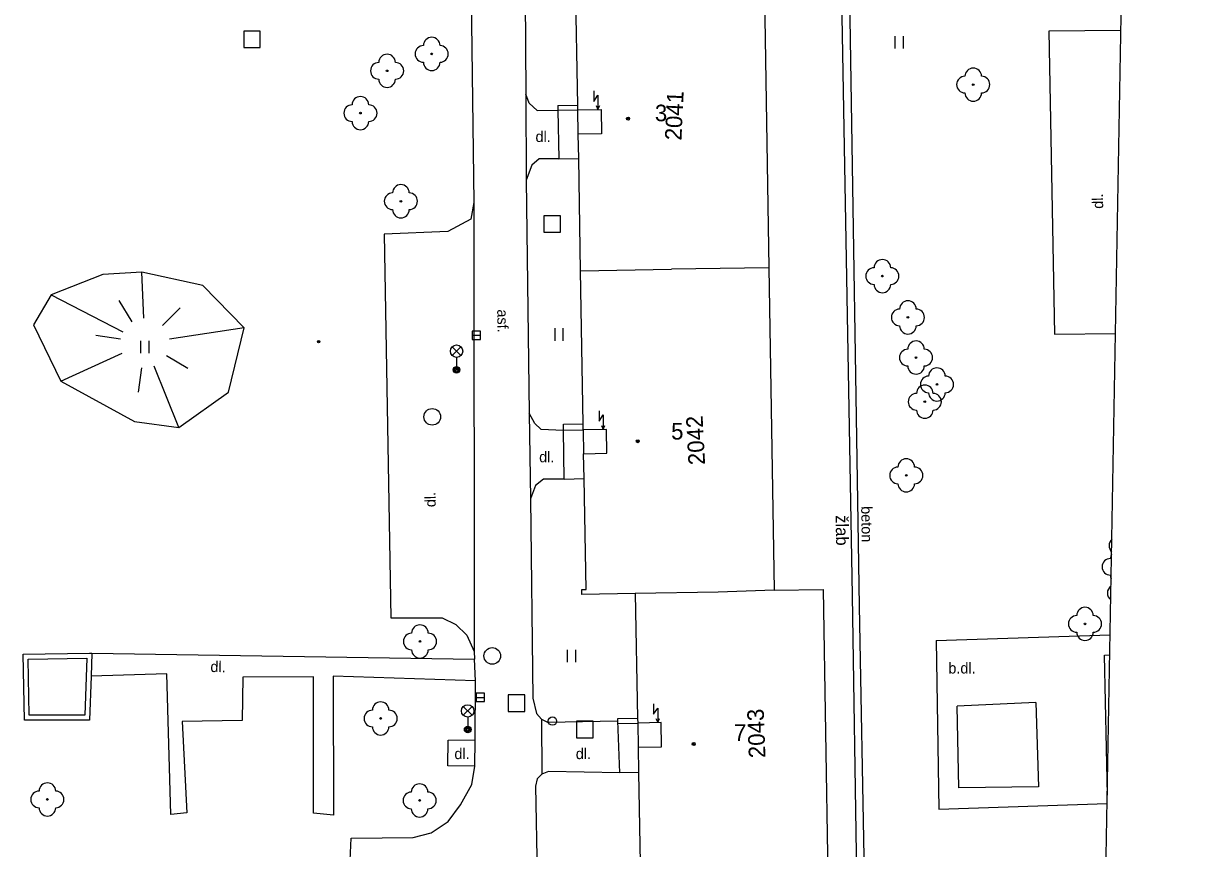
# Model space of a CAD drawing. Extents: x -641829 to -641525, y -1114855 to -1114359.
# Drawn here: x -641595.2 to -641525.3, y -1114618.1 to -1114568.4 of the extents above; entities that cross this region are included whole.
import ezdxf

# ---------------------------------------------------------------- set-up
doc = ezdxf.new("R2010")
doc.units = 0
for name, color, linetype in [('Vrstva 1', 7, 'Continuous'), ('Vrstva 10', 7, 'Continuous'), ('Vrstva 11', 7, 'Continuous'), ('Vrstva 14', 7, 'Continuous'), ('Vrstva 15', 7, 'Continuous'), ('Vrstva 20', 7, 'Continuous'), ('Vrstva 22', 7, 'Continuous'), ('Vrstva 24', 7, 'Continuous'), ('Vrstva 26', 7, 'Continuous'), ('Vrstva 27', 7, 'Continuous'), ('Vrstva 28', 7, 'Continuous'), ('Vrstva 33', 7, 'Continuous'), ('Vrstva 36', 7, 'Continuous'), ('Vrstva 39', 7, 'Continuous'), ('Vrstva 40', 7, 'Continuous'), ('Vrstva 42', 7, 'Continuous'), ('Vrstva 46', 7, 'Continuous'), ('Vrstva 47', 7, 'Continuous'), ('Vrstva 5', 7, 'Continuous')]:
    doc.layers.add(name, color=color, linetype=linetype)

msp = doc.modelspace()

# ---------------------------------------------------------------- linework, layer by layer
at = {"layer": 'Vrstva 1'}
msp.add_line((-641533.66, -1114832.21), (-641525.3, -1114362.64), dxfattribs=at)
at = {"layer": 'Vrstva 10'}
for p, q in [((-641564.94, -1114557.27), (-641564.87, -1114572.64)), ((-641568.18, -1114564.7), (-641568.01, -1114579.17)), ((-641564.87, -1114572.64), (-641564.84, -1114577.82)), ((-641564.84, -1114577.82), (-641564.66, -1114591.88)), ((-641568.01, -1114579.17), (-641567.97, -1114606.24)), ((-641564.66, -1114591.88), (-641564.58, -1114597.03)), ((-641564.58, -1114597.03), (-641564.44, -1114609.04)), ((-641567.97, -1114606.24), (-641567.96, -1114606.7)), ((-641567.9, -1114608), (-641567.96, -1114606.7)), ((-641567.91, -1114611.55), (-641567.9, -1114608)), ((-641564.44, -1114609.04), (-641564.23, -1114609.98)), ((-641564.23, -1114609.98), (-641563.92, -1114610.31)), ((-641563.92, -1114610.31), (-641563.89, -1114613.62)), ((-641567.93, -1114613.15), (-641567.91, -1114611.55)), ((-641568.13, -1114614.24), (-641567.93, -1114613.15)), ((-641564.18, -1114613.91), (-641564.29, -1114614.35)), ((-641563.89, -1114613.62), (-641564.18, -1114613.91)), ((-641568.8, -1114615.48), (-641568.13, -1114614.24)), ((-641564.29, -1114614.35), (-641564.01, -1114628.78)), ((-641569.55, -1114616.47), (-641568.8, -1114615.48)), ((-641570.58, -1114617.17), (-641569.55, -1114616.47)), ((-641571.65, -1114617.45), (-641570.58, -1114617.17)), ((-641575.8, -1114626.45), (-641575.4, -1114617.49)), ((-641575.4, -1114617.49), (-641571.65, -1114617.45))]:
    msp.add_line(p, q, dxfattribs=at)
at = {"layer": 'Vrstva 11'}
for p, q in [((-641544.73, -1114603.5), (-641545.7, -1114543.89)), ((-641546.21, -1114544.41), (-641545.19, -1114602.86)), ((-641528.971, -1114568.817), (-641533.32, -1114568.84)), ((-641533.32, -1114568.84), (-641532.97, -1114587.11)), ((-641564.67, -1114573.19), (-641564.87, -1114572.64)), ((-641564.67, -1114573.19), (-641564.19, -1114573.64)), ((-641562.94, -1114573.32), (-641561.73, -1114573.3)), ((-641562.94, -1114573.32), (-641562.93, -1114573.62)), ((-641564.19, -1114573.64), (-641562.93, -1114573.62)), ((-641562.93, -1114573.62), (-641561.72, -1114573.6)), ((-641562.93, -1114573.62), (-641562.88, -1114576.55)), ((-641564.06, -1114576.54), (-641564.51, -1114576.92)), ((-641562.88, -1114576.55), (-641564.06, -1114576.54)), ((-641562.88, -1114576.55), (-641561.67, -1114576.53)), ((-641564.51, -1114576.92), (-641564.84, -1114577.82)), ((-641568.01, -1114579.17), (-641568.18, -1114580.17)), ((-641568.18, -1114580.17), (-641569.56, -1114580.92)), ((-641569.56, -1114580.92), (-641573.41, -1114581.09)), ((-641573.41, -1114581.09), (-641573.01, -1114604.2)), ((-641532.97, -1114587.11), (-641529.296, -1114587.071)), ((-641564.32, -1114592.5), (-641564.66, -1114591.88)), ((-641564.32, -1114592.5), (-641563.95, -1114592.84)), ((-641563.95, -1114592.84), (-641562.6, -1114592.89)), ((-641562.6, -1114592.53), (-641561.4, -1114592.51)), ((-641562.6, -1114592.89), (-641562.6, -1114592.53)), ((-641562.6, -1114592.89), (-641561.4, -1114592.87)), ((-641562.55, -1114595.84), (-641562.6, -1114592.89)), ((-641564.29, -1114596.23), (-641564.58, -1114597.03)), ((-641563.8, -1114595.85), (-641564.29, -1114596.23)), ((-641562.55, -1114595.84), (-641563.8, -1114595.85)), ((-641562.55, -1114595.84), (-641561.35, -1114595.81)), ((-641545.19, -1114602.86), (-641544.57, -1114641.53)), ((-641544.03, -1114641.87), (-641544.73, -1114603.5)), ((-641573.01, -1114604.2), (-641569.91, -1114604.21)), ((-641569.91, -1114604.21), (-641569.08, -1114604.61)), ((-641569.08, -1114604.61), (-641568.43, -1114605.24)), ((-641568.43, -1114605.24), (-641567.97, -1114606.24)), ((-641540.11, -1114605.58), (-641529.619, -1114605.221)), ((-641540.11, -1114605.58), (-641539.95, -1114615.74)), ((-641595.18, -1114606.39), (-641591.17, -1114606.33)), ((-641595.11, -1114610.38), (-641595.18, -1114606.39)), ((-641594.87, -1114606.69), (-641591.34, -1114606.63)), ((-641594.82, -1114610.08), (-641594.87, -1114606.69)), ((-641591.34, -1114606.63), (-641591.47, -1114610.07)), ((-641591.17, -1114606.33), (-641591.03, -1114606.33)), ((-641591.03, -1114606.33), (-641591.08, -1114607.73)), ((-641591.03, -1114606.33), (-641567.96, -1114606.7)), ((-641529.97, -1114606.45), (-641529.64, -1114606.439)), ((-641529.791, -1114614.887), (-641529.97, -1114606.45)), ((-641586.52, -1114607.59), (-641591.08, -1114607.73)), ((-641586.28, -1114616.05), (-641586.52, -1114607.59)), ((-641591.08, -1114607.73), (-641591.18, -1114610.37)), ((-641581.94, -1114607.78), (-641581.98, -1114610.39)), ((-641577.66, -1114607.76), (-641581.94, -1114607.78)), ((-641577.66, -1114615.98), (-641577.66, -1114607.76)), ((-641576.48, -1114607.73), (-641576.47, -1114616.09)), ((-641567.9, -1114608), (-641576.48, -1114607.73)), ((-641534.11, -1114609.3), (-641538.85, -1114609.53)), ((-641538.74, -1114614.46), (-641538.85, -1114609.53)), ((-641534.11, -1114609.3), (-641533.94, -1114614.38)), ((-641591.18, -1114610.37), (-641595.11, -1114610.38)), ((-641591.47, -1114610.07), (-641594.82, -1114610.08)), ((-641581.98, -1114610.39), (-641585.59, -1114610.46)), ((-641563.92, -1114610.31), (-641563.55, -1114610.49)), ((-641563.55, -1114610.49), (-641559.32, -1114610.42)), ((-641559.32, -1114610.27), (-641558.12, -1114610.25)), ((-641559.32, -1114610.42), (-641559.32, -1114610.27)), ((-641559.2, -1114613.55), (-641559.32, -1114610.42)), ((-641585.59, -1114610.46), (-641585.31, -1114615.96)), ((-641559.31, -1114610.57), (-641558.11, -1114610.55)), ((-641569.57, -1114613.12), (-641569.55, -1114611.58)), ((-641569.55, -1114611.58), (-641567.91, -1114611.55)), ((-641567.93, -1114613.15), (-641569.57, -1114613.12)), ((-641563.49, -1114613.47), (-641563.89, -1114613.62)), ((-641559.2, -1114613.55), (-641563.49, -1114613.47)), ((-641558.06, -1114613.53), (-641559.2, -1114613.55)), ((-641533.94, -1114614.38), (-641538.74, -1114614.46)), ((-641585.31, -1114615.96), (-641586.28, -1114616.05)), ((-641576.47, -1114616.09), (-641577.66, -1114615.98)), ((-641539.95, -1114615.74), (-641529.8, -1114615.401))]:
    msp.add_line(p, q, dxfattribs=at)
at = {"layer": 'Vrstva 14'}
for p, q in [((-641590.37, -1114583.51), (-641593.5, -1114584.73)), ((-641588.03, -1114583.38), (-641590.37, -1114583.51)), ((-641584.34, -1114584.17), (-641588.03, -1114583.38)), ((-641581.85, -1114586.73), (-641584.34, -1114584.17)), ((-641593.5, -1114584.73), (-641594.55, -1114586.54)), ((-641594.55, -1114586.54), (-641592.91, -1114589.94)), ((-641582.8, -1114590.6), (-641581.85, -1114586.73)), ((-641592.91, -1114589.94), (-641588.47, -1114592.37)), ((-641585.79, -1114592.74), (-641582.8, -1114590.6)), ((-641588.47, -1114592.37), (-641585.79, -1114592.74))]:
    msp.add_line(p, q, dxfattribs=at)
at = {"layer": 'Vrstva 15'}
for p, q in [((-641587.9, -1114586.14), (-641588.03, -1114583.38)), ((-641593.5, -1114584.73), (-641589.17, -1114586.96)), ((-641589.41, -1114585.08), (-641588.62, -1114586.36)), ((-641586.77, -1114586.58), (-641585.71, -1114585.53)), ((-641590.8, -1114587.16), (-641589.32, -1114587.4)), ((-641581.85, -1114586.73), (-641586.35, -1114587.42)), ((-641592.91, -1114589.94), (-641589.2, -1114588.26)), ((-641586.54, -1114588.4), (-641585.25, -1114589.16)), ((-641588.04, -1114589.13), (-641588.24, -1114590.61)), ((-641585.79, -1114592.74), (-641587.28, -1114589.03))]:
    msp.add_line(p, q, dxfattribs=at)
at = {"layer": 'Vrstva 20'}
for radius in [0.075, 0.0204]:
    msp.add_circle((-641577.36, -1114587.56), radius, dxfattribs=at)
at = {"layer": 'Vrstva 22'}
for centre in [(-641570.54, -1114570.22), (-641573.23, -1114571.24), (-641537.88, -1114572.07), (-641574.84, -1114573.79), (-641572.4, -1114579.1), (-641543.36, -1114583.61), (-641541.82, -1114586.1), (-641541.33, -1114588.52), (-641540.07, -1114590.14), (-641540.8, -1114591.18), (-641541.92, -1114595.62), (-641531.14, -1114604.57), (-641571.25, -1114605.63), (-641573.62, -1114610.27), (-641593.72, -1114615.15), (-641571.27, -1114615.21)]:
    msp.add_circle(centre, 0.05, dxfattribs=at)
for centre, start, end in [((-641570.54, -1114569.72), 0, 180), ((-641571.04, -1114570.22), 90, 270), ((-641570.04, -1114570.22), 270, 90), ((-641573.23, -1114570.74), 0, 180), ((-641573.73, -1114571.24), 90, 270), ((-641572.73, -1114571.24), 270, 90), ((-641570.54, -1114570.72), 180, 0), ((-641537.88, -1114571.57), 0, 180), ((-641573.23, -1114571.74), 180, 0), ((-641538.38, -1114572.07), 90, 270), ((-641537.38, -1114572.07), 270, 90), ((-641537.88, -1114572.57), 180, 0), ((-641575.34, -1114573.79), 90, 270), ((-641574.84, -1114573.29), 0, 180), ((-641574.34, -1114573.79), 270, 90), ((-641574.84, -1114574.29), 180, 0), ((-641572.4, -1114578.6), 0, 180), ((-641572.9, -1114579.1), 90, 270), ((-641571.9, -1114579.1), 270, 90), ((-641572.4, -1114579.6), 180, 0), ((-641543.86, -1114583.61), 90, 270), ((-641543.36, -1114583.11), 0, 180), ((-641542.86, -1114583.61), 270, 90), ((-641543.36, -1114584.11), 180, 0), ((-641541.82, -1114585.6), 0, 180), ((-641542.32, -1114586.1), 90, 270), ((-641541.32, -1114586.1), 270, 90), ((-641541.82, -1114586.6), 180, 0), ((-641541.83, -1114588.52), 90, 270), ((-641541.33, -1114588.02), 0, 180), ((-641540.83, -1114588.52), 270, 90), ((-641541.33, -1114589.02), 180, 0), ((-641540.07, -1114589.64), 0, 180), ((-641540.8, -1114590.68), 0, 180), ((-641540.57, -1114590.14), 90, 270), ((-641539.57, -1114590.14), 270, 90), ((-641541.3, -1114591.18), 90, 270), ((-641540.07, -1114590.64), 180, 0), ((-641540.3, -1114591.18), 270, 90), ((-641540.8, -1114591.68), 180, 0), ((-641541.92, -1114595.12), 0, 180), ((-641542.42, -1114595.62), 90, 270), ((-641541.42, -1114595.62), 270, 90), ((-641541.92, -1114596.12), 180, 0), ((-641529.19, -1114599.85), 130.75768, 227.2024), ((-641529.61, -1114601.13), 90, 270), ((-641529.11, -1114600.63), 147.62785, 180), ((-641529.11, -1114601.63), 180, 206.15869), ((-641529.29, -1114602.71), 123.59741, 234.36268), ((-641531.64, -1114604.57), 90, 270), ((-641531.14, -1114604.07), 0, 180), ((-641530.64, -1114604.57), 270, 90), ((-641571.25, -1114605.13), 0, 180), ((-641571.75, -1114605.63), 90, 270), ((-641570.75, -1114605.63), 270, 90), ((-641531.14, -1114605.07), 180, 0), ((-641571.25, -1114606.13), 180, 0), ((-641573.62, -1114609.77), 0, 180), ((-641574.12, -1114610.27), 90, 270), ((-641573.12, -1114610.27), 270, 90), ((-641573.62, -1114610.77), 180, 0), ((-641594.22, -1114615.15), 90, 270), ((-641593.72, -1114614.65), 0, 180), ((-641593.22, -1114615.15), 270, 90), ((-641571.27, -1114614.71), 0, 180), ((-641571.77, -1114615.21), 90, 270), ((-641570.77, -1114615.21), 270, 90), ((-641593.72, -1114615.65), 180, 0), ((-641571.27, -1114615.71), 180, 0)]:
    msp.add_arc(centre, 0.5, start, end, dxfattribs=at)
at = {"layer": 'Vrstva 24'}
for p, q in [((-641560.77, -1114572.454), (-641560.77, -1114573.08)), ((-641560.77, -1114573.08), (-641560.52, -1114572.705)), ((-641560.52, -1114572.705), (-641560.52, -1114573.58)), ((-641560.63, -1114573.335), (-641560.52, -1114573.58)), ((-641560.52, -1114573.58), (-641560.41, -1114573.335)), ((-641560.45, -1114591.724), (-641560.45, -1114592.35)), ((-641560.45, -1114592.35), (-641560.2, -1114591.975)), ((-641560.2, -1114591.975), (-641560.2, -1114592.85)), ((-641560.31, -1114592.605), (-641560.2, -1114592.85)), ((-641560.2, -1114592.85), (-641560.09, -1114592.605)), ((-641557.16, -1114609.394), (-641557.16, -1114610.02)), ((-641557.16, -1114610.02), (-641556.91, -1114609.645)), ((-641556.91, -1114609.645), (-641556.91, -1114610.52)), ((-641557.02, -1114610.275), (-641556.91, -1114610.52)), ((-641556.91, -1114610.52), (-641556.8, -1114610.275))]:
    msp.add_line(p, q, dxfattribs=at)
at = {"layer": 'Vrstva 26'}
for points in [[(-641581.88, -1114569.84), (-641580.88, -1114569.84), (-641580.88, -1114568.84), (-641581.88, -1114568.84)], [(-641563.78, -1114580.97), (-641562.78, -1114580.97), (-641562.78, -1114579.97), (-641563.78, -1114579.97)], [(-641565.92, -1114609.85), (-641564.92, -1114609.85), (-641564.92, -1114608.85), (-641565.92, -1114608.85)], [(-641561.8, -1114611.43), (-641560.8, -1114611.43), (-641560.8, -1114610.43), (-641561.8, -1114610.43)]]:
    msp.add_lwpolyline(points, close=True, dxfattribs=at)
at = {"layer": 'Vrstva 27'}
for p, q in [((-641568.1, -1114587.18), (-641567.6, -1114587.18)), ((-641567.85, -1114609), (-641567.35, -1114609))]:
    msp.add_line(p, q, dxfattribs=at)
for points in [[(-641568.1, -1114587.43), (-641567.6, -1114587.43), (-641567.6, -1114586.93), (-641568.1, -1114586.93)], [(-641567.85, -1114609.25), (-641567.35, -1114609.25), (-641567.35, -1114608.75), (-641567.85, -1114608.75)]]:
    msp.add_lwpolyline(points, close=True, dxfattribs=at)
for centre in [(-641570.51, -1114592.09), (-641566.89, -1114606.5)]:
    msp.add_circle(centre, 0.5, dxfattribs=at)
at = {"layer": 'Vrstva 28'}
msp.add_circle((-641563.26, -1114610.43), 0.25, dxfattribs=at)
at = {"layer": 'Vrstva 33'}
for p, q in [((-641569.305, -1114588.4), (-641568.775, -1114587.87)), ((-641569.305, -1114587.87), (-641568.775, -1114588.4)), ((-641569.04, -1114588.51), (-641569.04, -1114589.26)), ((-641568.635, -1114610.08), (-641568.105, -1114609.55)), ((-641568.635, -1114609.55), (-641568.105, -1114610.08)), ((-641568.37, -1114610.19), (-641568.37, -1114610.94))]:
    msp.add_line(p, q, dxfattribs=at)
for centre, radius in [((-641569.04, -1114588.135), 0.375), ((-641569.04, -1114589.26), 0.2), ((-641569.04, -1114589.26), 0.145), ((-641569.04, -1114589.26), 0.0876), ((-641568.37, -1114609.815), 0.375), ((-641568.37, -1114610.94), 0.2), ((-641568.37, -1114610.94), 0.145), ((-641568.37, -1114610.94), 0.0876)]:
    msp.add_circle(centre, radius, dxfattribs=at)
at = {"layer": 'Vrstva 36'}
for p, q in [((-641542.594, -1114569.902), (-641542.594, -1114569.154)), ((-641542.094, -1114569.902), (-641542.094, -1114569.154)), ((-641563.104, -1114587.502), (-641563.104, -1114586.754)), ((-641562.604, -1114587.502), (-641562.604, -1114586.754)), ((-641588.074, -1114588.264), (-641588.074, -1114587.512)), ((-641587.574, -1114588.264), (-641587.574, -1114587.512)), ((-641562.344, -1114606.882), (-641562.344, -1114606.134)), ((-641561.844, -1114606.882), (-641561.844, -1114606.134))]:
    msp.add_line(p, q, dxfattribs=at)
at = {"layer": 'Vrstva 39'}
for centre, radius in [((-641558.7, -1114574.12), 0.09), ((-641558.7, -1114574.12), 0.0398), ((-641558.11, -1114593.56), 0.09), ((-641558.11, -1114593.56), 0.0398), ((-641554.74, -1114611.81), 0.09), ((-641554.74, -1114611.81), 0.0398)]:
    msp.add_circle(centre, radius, dxfattribs=at)
at = {"layer": 'Vrstva 5'}
for p, q in [((-641550.49, -1114565.62), (-641550.21, -1114583.11)), ((-641561.72, -1114573.6), (-641560.32, -1114573.58)), ((-641561.7, -1114575.05), (-641561.72, -1114573.6)), ((-641560.32, -1114573.58), (-641560.3, -1114575.03)), ((-641560.3, -1114575.03), (-641561.7, -1114575.05)), ((-641561.56, -1114583.29), (-641556.08, -1114583.2)), ((-641550.21, -1114583.11), (-641556.08, -1114583.2)), ((-641550.21, -1114583.11), (-641549.89, -1114602.53)), ((-641560, -1114592.85), (-641561.4, -1114592.87)), ((-641561.4, -1114592.87), (-641561.38, -1114594.32)), ((-641559.98, -1114594.29), (-641560, -1114592.85)), ((-641561.38, -1114594.32), (-641559.98, -1114594.29)), ((-641561.48, -1114602.49), (-641561.23, -1114602.49)), ((-641561.48, -1114602.79), (-641561.48, -1114602.49)), ((-641558.26, -1114602.74), (-641561.48, -1114602.79)), ((-641553.26, -1114602.66), (-641558.26, -1114602.74)), ((-641549.89, -1114602.53), (-641553.26, -1114602.66)), ((-641549.89, -1114602.53), (-641546.94, -1114602.5)), ((-641546.94, -1114602.5), (-641546.61, -1114622.07)), ((-641556.71, -1114610.52), (-641558.11, -1114610.55)), ((-641558.11, -1114610.55), (-641558.08, -1114612)), ((-641556.68, -1114611.98), (-641556.71, -1114610.52)), ((-641558.08, -1114612), (-641556.68, -1114611.98))]:
    msp.add_line(p, q, dxfattribs=at)
for points in [[(-641561.72, -1114573.6), (-641561.73, -1114573.3), (-641561.86, -1114565.81)], [(-641561.56, -1114583.29), (-641561.67, -1114576.53), (-641561.7, -1114575.05)], [(-641561.4, -1114592.87), (-641561.4, -1114592.51), (-641561.56, -1114583.29)], [(-641561.23, -1114602.49), (-641561.35, -1114595.81), (-641561.38, -1114594.32)], [(-641558.26, -1114602.74), (-641558.12, -1114610.25), (-641558.11, -1114610.55)], [(-641558.08, -1114612), (-641558.06, -1114613.53), (-641557.9, -1114622.27)]]:
    msp.add_lwpolyline(points, dxfattribs=at)

# ---------------------------------------------------------------- texts
at = {"layer": 'Vrstva 40'}
for s, p in [('dl.', (-641564.28, -1114575.53)), ('dl.', (-641564.06, -1114594.83)), ('b.dl.', (-641539.38, -1114607.56)), ('dl.', (-641569.17, -1114612.72)), ('dl.', (-641561.85, -1114612.72))]:
    msp.add_text(s, height=0.65, dxfattribs=at).set_placement(p)
for s, rotation, p in [('dl.', 90.87947, (-641530.04, -1114579.55)), ('asf.', 270.87299, (-641566.59, -1114585.62)), ('dl.', 90.99161, (-641570.3, -1114597.53)), ('beton', 270.97407, (-641544.64, -1114597.48)), ('dl.', 359.07792, (-641583.89, -1114607.47))]:
    msp.add_text(s, height=0.65, rotation=rotation, dxfattribs=at).set_placement(p)
at = {"layer": 'Vrstva 42'}
msp.add_text('žlab', height=0.75, rotation=270.97407, dxfattribs=at).set_placement((-641546.18, -1114598.02))
at = {"layer": 'Vrstva 46'}
for s, p in [('3', (-641557.08, -1114574.28)), ('5', (-641556.1, -1114593.46)), ('7', (-641552.31, -1114611.62))]:
    msp.add_text(s, height=1, dxfattribs=at).set_placement(p)
at = {"layer": 'Vrstva 47'}
for s, height, rotation, p in [('2041', 0.9999, 87.35266, (-641555.48, -1114575.45)), ('2042', 0.9999, 93.02771, (-641554.05, -1114594.97)), ('2043', 1, 92.12792, (-641550.41, -1114612.64))]:
    msp.add_text(s, height=height, rotation=rotation, dxfattribs=at).set_placement(p)

doc.saveas('drawing.dxf')
